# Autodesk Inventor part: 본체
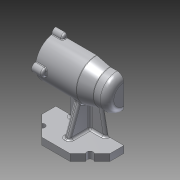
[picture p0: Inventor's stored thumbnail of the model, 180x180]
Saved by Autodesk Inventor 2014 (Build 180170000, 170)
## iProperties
Created: 2021-01
Part Number: 본체
Material: Aluminum 6061
Document SubType Name: Modeling
Designer: kh
Density: 2.71 g/cm^3
Appearance: Aluminum - Flat
Mass: 632.152 g
Surface Area: 614.087 cm^2
Volume: 233.266 cm^3
Author: kh
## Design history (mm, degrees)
sketch "Sketch1" dims "d0" = 100
  geometry: L1 (0, 0)-(0, 50); L2 (20.711, 50)-(50, 20.711); L3 (50, 20.711)-(50, -20.711); L4 (50, -20.711)-(20.711, -50); L5 (20.711, -50)-(-20.711, -50); L6 (-20.711, -50)-(-50, -20.711); L7 (-50, -20.711)-(-50, 20.711); L8 (-50, 20.711)-(-20.711, 50); L9 (-20.711, 50)-(20.711, 50); L10 (0, 0)-(-35.355, 35.355); 2 further points
  constraints: 20 end point, 3 coincident, 2 midpoint, 1 perpendicular, 1 vertical, 1 vertical alignment, 19 other
extrude "Extrusion1" new body sketch "Sketch1" distance "d1" = 10; taper "d2" = 0 deg
sketch "Sketch2"
  geometry: 2 further points
hole "Hole1" sketch "Sketch2" at (-35.355, 35.355) diameter "d3" = 9; stored, may be unused: countersink angle "d7" = 90 deg, drill point angle "d9" = 118 deg; dims "d4" = 6, "d5" = 4, "d6" = 2, "d8" = 8
pattern_circular "Circular Pattern1" dims angle "d11" = 360 deg
sketch "Sketch3"
  geometry: L1 (-50, 75)-(50, 75); L2 (50, 75)-(50, 105); L3 (50, 105)-(-10, 105); L4 (-10, 105)-(-30, 100); L5 (-30, 100)-(-50, 100); L6 (-50, 100)-(-50, 75); L7 (50, 0)-(50, 10) reference; L8 (50, 96)-(35, 96); L9 (35, 96)-(35, 99); L10 (35, 99)-(-7, 99); L11 (-7, 99)-(-7, 96); L12 (-7, 96)-(-19, 96); L13 (-19, 96)-(-19, 92.5); L14 (-19, 92.5)-(-37, 92.5); L15 (-37, 92.5)-(-37, 91); L16 (-37, 91)-(-41, 91); L17 (-41, 91)-(-41, 85.5); L18 (-41, 85.5)-(-44, 85.5); L19 (-44, 85.5)-(-44, 75); L20 (-44, 75)-(50, 75); L21 (50, 96)-(50, 75); 3 further points
  constraints: 40 end point, 10 parallel, 6 perpendicular, 2 collinear, 2 midpoint, 2 point on line, 1 horizontal, 1 vertical alignment
  dimensions: "d13" = 60 diameter of L3 L1; "d14" = 50 diameter of L5 L1; "d15" = 75 vertical distance of point (0, 0) L1.start; "d16" = 20 distance of L4.end L5.end; "d17" = 100 distance between parallel lines of L6 L2; "d18" = 40 horizontal distance of L5.end L3.end; "d19" = 42 diameter of L8 L20; "d20" = 48 diameter of L10 L1; "d21" = 42 diameter of L12 L1; "d22" = 35 diameter of L14 L20; "d23" = 32 diameter of L16 L20; "d24" = 21 diameter of L18 L1; "d25" = 15 distance of L8.start L8.end; "d26" = 42 distance of L9.end L10.end; "d27" = 12 distance of L11.end L12.end; "d28" = 3 distance of L17.end L18.end; "d29" = 4 distance of L15.end L16.end; "d30" = 18 distance of L13.end L14.end
revolve "Revolution1" sketch "Sketch3" stored, may be unused: angle "d31" = 90 deg
sketch "Sketch4"
  geometry: L1 (0, -4)-(-27, -4); L2 (-27, -4)-(-27, 4); L3 (-27, 4)-(0, 4); L4 (0, 4)-(0, -4); L5 (-50, -20.711)-(-50, 20.711) reference; 2 further points
  constraints: 8 end point, 2 parallel, 1 coincident, 1 horizontal, 1 midpoint, 1 perpendicular
  dimensions: "d32" = 8 distance of L1.end L2.end; "d33" = 23 distance between parallel lines of L2 L5
extrude "Extrusion2" join sketch "Sketch4" stored distance "d34" = 10; taper "d35" = 0 deg
sketch "Sketch5"
  geometry: L1 (-20.711, 10)-(-32.173, 10) reference; L2 (-38.537, 10)-(-30.855, 10) reference; L3 (-38.537, 10)-(-50, 10) reference; L4 (20.711, 10)-(-20.711, 10) reference; L5 (-27, 10)-(-20.233, 44.813); 1 further point
  constraints: 2 end point, 1 point on line
  dimensions: "d36" = 23 distance of L5.start L3.end; "d37" = 101 deg angle of L1 L5
feature "Rib1" sketch "Sketch5" dims "d38" = 1, "d39" = 8, "d40" = 0, "d41" = 0, "d42" = 1, "d43" = 1
sketch "Sketch6"
  geometry: L1 (-50, 10)-(-38.537, 10) reference; L2 (-35, 10)-(-21.146, 48.062); 1 further point
  constraints: 2 end point, 1 point on line
  dimensions: "d44" = 15 distance of L1.start L2.start; "d45" = 110 deg angle of L2 L1
feature "Rib2" sketch "Sketch6" dims "d46" = 1, "d47" = 8, "d48" = 0, "d49" = 0, "d50" = 1, "d51" = 1
mirror "Mirror1"
sketch "Sketch7"
  geometry: L1 (0, 0)-(30, 0); C1 r 6 at (30, 0); 1 further point
  constraints: 2 end point, 1 centre point, 1 coincident, 1 horizontal, 1 horizontal alignment, 1 other
  dimensions: "d52" = 12 diameter of C1
extrude "Extrusion3" join sketch "Sketch7" distance "d53" = 16; taper "d54" = 0 deg
fillet "Fillet1" dims "d55" = 3
fillet "Fillet2" dims "d56" = 1
pattern_circular "Circular Pattern2" dims "d58" = 360 deg
hole "Hole2" diameter "d62" = 3.459; stored, may be unused: countersink angle "d66" = 90 deg, drill point angle "d68" = 118 deg; dims "d60" = 10, "d61" = 10, "d63" = 8, "d64" = 4, "d65" = 2, "d67" = 10
pattern_circular "Circular Pattern3" dims angle "d70" = 360 deg
fillet "Fillet3" dims "d72" = 0.3, "d73" = 3
chamfer "Chamfer1" distance "d74" = 1; stored, may be unused: second distance "d75" = 2, angle "d76" = 45 deg
fillet "Fillet4" dims "d77" = 10
fillet "Fillet5" dims "d78" = 3
fillet "Fillet6" dims "d79" = 3
fillet "Fillet7" dims "d80" = 3
workplane "Work Plane1"
sketch "Sketch9"
  geometry: L1 (30, 6.771)-(30, 29.226) reference; L2 (30, 5.998)-(30, -5.998) reference; L3 (30, 0)-(-34.43, 0); 2 further points
  constraints: 2 end point, 1 midpoint, 1 perpendicular, 1 point on line, 1 other
  dimensions: "d81" = 38 distance from line of point (-8, 0) L1
emboss "Emboss1" sketch "Sketch9" dims "d82" = 0.5, "d83" = 0
body "Solid1"
